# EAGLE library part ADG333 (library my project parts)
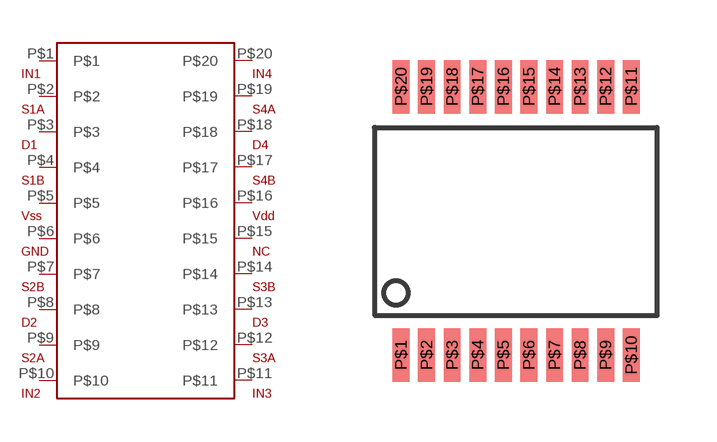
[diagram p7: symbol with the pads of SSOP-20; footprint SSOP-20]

Designator prefix -

## ADG333  [SSOP-20]
P$1  P$1
P$2  P$2
P$3  P$3
P$4  P$4
P$5  P$5
P$6  P$6
P$7  P$7
P$8  P$8
P$9  P$9
P$10  P$10
P$11  P$11
P$12  P$12
P$13  P$13
P$14  P$14
P$15  P$15
P$16  P$16
P$17  P$17
P$18  P$18
P$19  P$19
P$20  P$20

## Footprint SSOP-20 (pad centres in mm)
smd 0.42 x 1.34: P$1 -2.88,-3.36; P$2 -2.24,-3.36; P$3 -1.6,-3.36; P$4 -0.96,-3.36; P$5 -0.32,-3.36; P$6 0.32,-3.36; P$7 0.96,-3.36; P$8 1.6,-3.36; P$9 2.24,-3.36; P$10 2.88,-3.36; P$11 2.88,3.36; P$12 2.24,3.36; P$13 1.6,3.36; P$14 0.96,3.36; P$15 0.32,3.36; P$16 -0.32,3.36; P$17 -0.96,3.36; P$18 -1.6,3.36; P$19 -2.24,3.36; P$20 -2.88,3.36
